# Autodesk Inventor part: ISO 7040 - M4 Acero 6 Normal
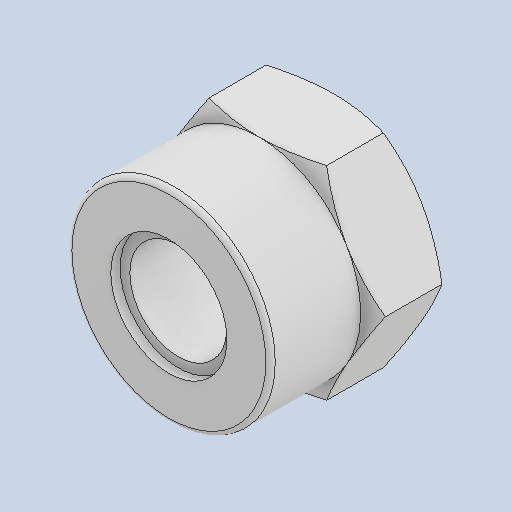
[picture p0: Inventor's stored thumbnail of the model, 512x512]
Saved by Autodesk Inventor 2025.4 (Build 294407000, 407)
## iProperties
Created: 2026-09
Part Number: ISO 7040 - M4 Acero 6 Normal
Material: Generic
Description: Tuerca autoblocante hexagonal normal ISO 7040 - M4
Document SubType Name: Modeling
Designer: AdminForWorker
Density: 1 g/cm^3
Appearance: Default
Title: Tuerca autoblocante hexagonal normal ISO 7040 - M4 Acero 6 Normal v1
Author: AdminForWorker
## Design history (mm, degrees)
feature "Body5"
feature "Body6"
body "Solid1"
body "Solid2"
